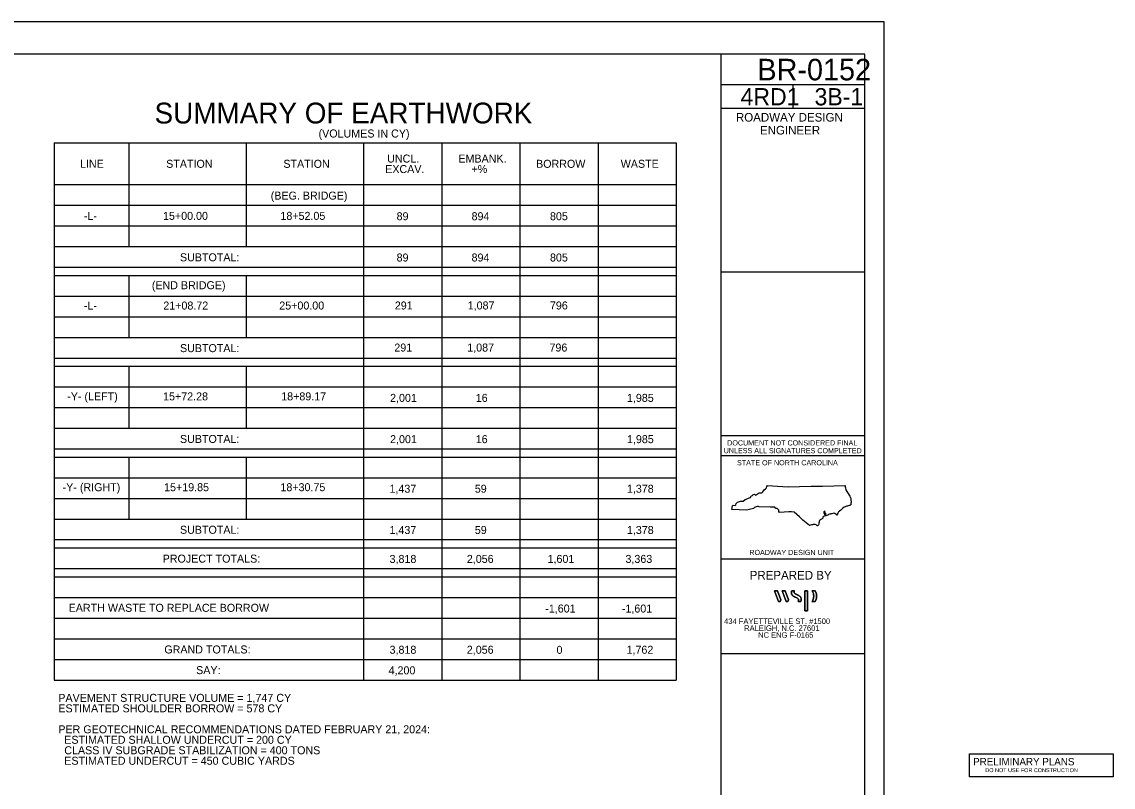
# Model space of a CAD drawing. Extents: x 1551694 to 1553358, y 810412 to 811095.
# Drawn here: x 1553203.1 to 1553355.1, y 810595.3 to 810701.9 of the extents above; entities that cross this region are included whole.
import ezdxf

# ---------------------------------------------------------------- set-up
doc = ezdxf.new("R2010")
doc.units = 0
for name, color, linetype in [('Construction Elements LEVEL', 7, 'Continuous'), ('Default', 7, 'Continuous'), ('Draft_Plan_Labels', 7, 'Continuous'), ('E_NCDOT_Vertical_Profile_Ground_Line', 7, 'Continuous'), ('P_HYD_Ditch_Flow_Arrow', 7, 'Continuous'), ('P_HYD_Pipe_RCP_15in_Class_III', 7, 'Continuous'), ('P_NCDOT_SS_Transition_Line', 7, 'Continuous'), ('Typical Terminator CELL', 7, 'Continuous'), ('V Ditch Special Lateral with PSRM Detail CELL', 7, 'Continuous')]:
    doc.layers.add(name, color=color, linetype=linetype)

msp = doc.modelspace()

# ---------------------------------------------------------------- linework, layer by layer
at = {"layer": 'Construction Elements LEVEL'}
for p, q in [((1553207.6, 810685.06), (1553294.23, 810685.06)), ((1553207.6, 810685.06), (1553207.6, 810610.26)), ((1553218.02, 810685.06), (1553218.02, 810670.63)), ((1553234.35, 810685.06), (1553234.35, 810670.63)), ((1553250.68, 810685.06), (1553250.68, 810610.26)), ((1553261.57, 810685.06), (1553261.57, 810610.26)), ((1553272.46, 810685.06), (1553272.46, 810610.26)), ((1553283.35, 810685.06), (1553283.35, 810610.26)), ((1553294.23, 810685.06), (1553294.23, 810610.26)), ((1553207.6, 810679.26), (1553294.23, 810679.26)), ((1553207.6, 810676.38), (1553294.23, 810676.38)), ((1553207.6, 810673.51), (1553294.23, 810673.51)), ((1553207.6, 810670.63), (1553294.23, 810670.63)), ((1553207.6, 810667.76), (1553294.23, 810667.76)), ((1553207.6, 810666.61), (1553294.23, 810666.61)), ((1553218.02, 810666.61), (1553218.02, 810657.98)), ((1553234.35, 810666.61), (1553234.35, 810657.98)), ((1553207.6, 810663.73), (1553294.23, 810663.73)), ((1553207.6, 810660.86), (1553294.23, 810660.86)), ((1553207.6, 810657.98), (1553294.23, 810657.98)), ((1553207.6, 810655.11), (1553294.23, 810655.11)), ((1553207.6, 810653.96), (1553294.23, 810653.96)), ((1553218.02, 810653.96), (1553218.02, 810645.33)), ((1553234.35, 810653.96), (1553234.35, 810645.33)), ((1553207.6, 810651.08), (1553294.23, 810651.08)), ((1553207.6, 810648.21), (1553294.23, 810648.21)), ((1553207.6, 810645.33), (1553294.23, 810645.33)), ((1553207.6, 810642.46), (1553294.23, 810642.46)), ((1553207.6, 810641.31), (1553294.23, 810641.31)), ((1553218.02, 810641.31), (1553218.02, 810632.68)), ((1553234.35, 810641.31), (1553234.35, 810632.68)), ((1553207.6, 810638.43), (1553294.23, 810638.43)), ((1553207.6, 810635.56), (1553294.23, 810635.56)), ((1553207.6, 810632.68), (1553294.23, 810632.68)), ((1553207.6, 810629.81), (1553294.23, 810629.81)), ((1553207.6, 810628.66), (1553294.23, 810628.66)), ((1553207.6, 810625.78), (1553294.23, 810625.78)), ((1553207.6, 810624.63), (1553294.23, 810624.63)), ((1553207.6, 810621.76), (1553294.23, 810621.76)), ((1553207.6, 810618.88), (1553294.23, 810618.88)), ((1553207.6, 810616.01), (1553294.23, 810616.01)), ((1553207.6, 810613.13), (1553294.23, 810613.13)), ((1553207.6, 810610.26), (1553294.23, 810610.26))]:
    msp.add_line(p, q, dxfattribs=at)
at = {"layer": 'Default'}
for p, q in [((1553308.47, 810621.19), (1553307.91, 810622.7)), ((1553307.91, 810622.7), (1553308.32, 810622.7)), ((1553308.32, 810622.7), (1553308.78, 810621.45)), ((1553309.56, 810621.19), (1553309, 810622.7)), ((1553309, 810622.7), (1553309.41, 810622.7)), ((1553309.41, 810622.7), (1553309.87, 810621.45)), ((1553312.12, 810619.91), (1553312.12, 810622.7)), ((1553312.12, 810622.7), (1553312.51, 810622.7)), ((1553312.51, 810622.7), (1553312.51, 810619.91)), ((1553308.69, 810621.19), (1553308.47, 810621.19)), ((1553308.78, 810621.45), (1553308.69, 810621.19)), ((1553309.77, 810621.19), (1553309.56, 810621.19)), ((1553309.87, 810621.45), (1553309.77, 810621.19)), ((1553312.51, 810619.91), (1553312.12, 810619.91))]:
    msp.add_line(p, q, dxfattribs=at)
for points in [[(1553308.32, 810622.7), (1553307.91, 810622.7), (1553308.47, 810621.19), (1553308.69, 810621.19), (1553308.78, 810621.45), (1553308.32, 810622.7)], [(1553309.41, 810622.7), (1553309, 810622.7), (1553309.56, 810621.19), (1553309.77, 810621.19), (1553309.87, 810621.45), (1553309.41, 810622.7)], [(1553312.51, 810619.91), (1553312.51, 810622.7), (1553312.12, 810622.7), (1553312.12, 810619.91), (1553312.51, 810619.91)]]:
    msp.add_lwpolyline(points, dxfattribs=at)
msp.add_lwpolyline([(1553335.08, 810596.79), (1553335.08, 810599.98), (1553355.08, 810599.98), (1553355.08, 810596.79)], close=True, dxfattribs=at)
for points in [[(1553310.28, 810622.48), (1553310.29, 810622.55), (1553310.3, 810622.63), (1553310.33, 810622.7), (1553310.33, 810622.7), (1553310.69, 810622.7), (1553310.69, 810622.7), (1553310.66, 810622.65), (1553310.63, 810622.55), (1553310.66, 810622.45), (1553310.69, 810622.37), (1553310.75, 810622.31), (1553310.83, 810622.26), (1553310.92, 810622.2), (1553311.02, 810622.17), (1553311.12, 810622.12), (1553311.22, 810622.07), (1553311.32, 810622.02), (1553311.41, 810621.95), (1553311.53, 810621.84), (1553311.61, 810621.71), (1553311.62, 810621.55), (1553311.62, 810621.53), (1553311.62, 810621.51), (1553311.62, 810621.49), (1553311.62, 810621.39), (1553311.6, 810621.29), (1553311.56, 810621.19), (1553311.56, 810621.19), (1553311.19, 810621.19), (1553311.19, 810621.19), (1553311.23, 810621.25), (1553311.26, 810621.34), (1553311.25, 810621.41), (1553311.24, 810621.6), (1553311.01, 810621.71), (1553310.81, 810621.79), (1553310.78, 810621.81), (1553310.76, 810621.82), (1553310.73, 810621.83), (1553310.64, 810621.87), (1553310.56, 810621.92), (1553310.49, 810621.98), (1553310.41, 810622.04), (1553310.35, 810622.1), (1553310.32, 810622.2), (1553310.29, 810622.28), (1553310.28, 810622.36), (1553310.28, 810622.45), (1553310.28, 810622.46), (1553310.28, 810622.47), (1553310.28, 810622.48)], [(1553310.28, 810622.48), (1553310.28, 810622.47), (1553310.28, 810622.46), (1553310.28, 810622.45), (1553310.28, 810622.36), (1553310.29, 810622.28), (1553310.32, 810622.2), (1553310.35, 810622.1), (1553310.41, 810622.04), (1553310.49, 810621.98), (1553310.56, 810621.92), (1553310.64, 810621.87), (1553310.73, 810621.83), (1553310.76, 810621.82), (1553310.78, 810621.81), (1553310.81, 810621.79), (1553311.01, 810621.71), (1553311.24, 810621.6), (1553311.25, 810621.41), (1553311.26, 810621.34), (1553311.23, 810621.25), (1553311.19, 810621.19), (1553311.19, 810621.19), (1553311.56, 810621.19), (1553311.56, 810621.19), (1553311.6, 810621.29), (1553311.62, 810621.39), (1553311.62, 810621.49), (1553311.62, 810621.51), (1553311.62, 810621.53), (1553311.62, 810621.55), (1553311.61, 810621.71), (1553311.53, 810621.84), (1553311.41, 810621.95), (1553311.32, 810622.02), (1553311.22, 810622.07), (1553311.12, 810622.12), (1553311.02, 810622.17), (1553310.92, 810622.2), (1553310.83, 810622.26), (1553310.75, 810622.31), (1553310.69, 810622.37), (1553310.66, 810622.45), (1553310.63, 810622.55), (1553310.66, 810622.65), (1553310.69, 810622.7), (1553310.69, 810622.7), (1553310.33, 810622.7), (1553310.33, 810622.7), (1553310.3, 810622.63), (1553310.29, 810622.55), (1553310.28, 810622.48)], [(1553313.37, 810621.95), (1553313.37, 810622.26), (1553313.26, 810622.53), (1553313.11, 810622.7), (1553313.11, 810622.7), (1553313.55, 810622.7), (1553313.55, 810622.7), (1553313.69, 810622.53), (1553313.78, 810622.23), (1553313.78, 810621.95), (1553313.78, 810621.95), (1553313.78, 810621.95), (1553313.78, 810621.95), (1553313.78, 810621.67), (1553313.69, 810621.37), (1553313.55, 810621.19), (1553313.55, 810621.19), (1553313.11, 810621.19), (1553313.11, 810621.19), (1553313.26, 810621.37), (1553313.37, 810621.63), (1553313.37, 810621.95), (1553313.37, 810621.95), (1553313.37, 810621.95), (1553313.37, 810621.95)], [(1553313.37, 810621.95), (1553313.37, 810621.95), (1553313.37, 810621.95), (1553313.37, 810621.95), (1553313.37, 810621.63), (1553313.26, 810621.37), (1553313.11, 810621.19), (1553313.11, 810621.19), (1553313.55, 810621.19), (1553313.55, 810621.19), (1553313.69, 810621.37), (1553313.78, 810621.67), (1553313.78, 810621.95), (1553313.78, 810621.95), (1553313.78, 810621.95), (1553313.78, 810621.95), (1553313.78, 810622.23), (1553313.69, 810622.53), (1553313.55, 810622.7), (1553313.55, 810622.7), (1553313.11, 810622.7), (1553313.11, 810622.7), (1553313.26, 810622.53), (1553313.37, 810622.26), (1553313.37, 810621.95)]]:
    msp.add_open_spline(points, degree=3, dxfattribs=at)
at = {"layer": 'Draft_Plan_Labels'}
msp.add_line((1553317.75, 810637.34), (1553317.75, 810637.35), dxfattribs=at)
for points in [[(1553301.95, 810634.02), (1553302.08, 810634.51), (1553302.16, 810634.6), (1553302.42, 810634.58), (1553302.51, 810634.67), (1553302.58, 810634.86), (1553302.78, 810635.02), (1553303.16, 810635.19), (1553303.55, 810635.19), (1553303.83, 810635.39), (1553304.2, 810635.55), (1553304.38, 810635.65), (1553304.56, 810635.66), (1553304.68, 810635.93), (1553304.86, 810635.98), (1553304.92, 810636.07), (1553305.11, 810636.16), (1553305.28, 810636.03), (1553305.37, 810636.04), (1553305.48, 810636.14), (1553305.76, 810636.34), (1553306.14, 810636.35), (1553306.31, 810636.49), (1553306.46, 810636.77), (1553306.64, 810636.9), (1553306.82, 810637.03), (1553306.85, 810637.21), (1553306.96, 810637.35)], [(1553306.96, 810637.35), (1553308.33, 810637.25), (1553309.84, 810637.19), (1553311.41, 810637.21), (1553313.01, 810637.24), (1553314.58, 810637.26), (1553316.2, 810637.31), (1553317.71, 810637.35), (1553317.75, 810637.35)], [(1553312.79, 810631.76), (1553311.87, 810632.52), (1553311.39, 810633.01), (1553310.67, 810633.63), (1553310.29, 810633.69), (1553309.9, 810633.67), (1553308.6, 810633.61), (1553308.53, 810633.71), (1553308.53, 810633.8), (1553308.52, 810633.9), (1553308.28, 810634.16), (1553308.1, 810634.14), (1553307.97, 810634.32), (1553307.3, 810634.33), (1553305.8, 810634.4), (1553305.7, 810634.42), (1553305.52, 810634.42), (1553305.15, 810634.29), (1553304.97, 810634.14), (1553304.42, 810634.03), (1553304.03, 810633.94), (1553302.98, 810633.95), (1553301.95, 810634.02)]]:
    msp.add_lwpolyline(points, dxfattribs=at)
for points in [[(1553317.75, 810637.34), (1553317.78, 810637.04), (1553318.33, 810635.99), (1553318.53, 810635.52), (1553318.57, 810635.04), (1553318.55, 810634.73)], [(1553318.55, 810634.73), (1553318.5, 810634.64), (1553318.41, 810634.59), (1553317.95, 810634.46)], [(1553317.95, 810634.46), (1553317.6, 810634.32), (1553316.98, 810633.78), (1553316.73, 810633.51), (1553316.61, 810633.24), (1553316.34, 810633.44), (1553315.77, 810633.39), (1553315.56, 810633.36), (1553315.11, 810633.15), (1553315.02, 810633.21), (1553315.01, 810633.3), (1553315.09, 810633.39), (1553314.96, 810633.55), (1553314.99, 810633.64), (1553314.84, 810633.76), (1553314.79, 810633.67), (1553314.79, 810633.49), (1553314.87, 810633.4), (1553314.87, 810633.31), (1553314.99, 810633.13), (1553314.68, 810633.02), (1553314.65, 810632.82), (1553314.37, 810632.64), (1553314.12, 810632.24), (1553313.97, 810631.78), (1553313.89, 810631.74), (1553313.71, 810631.88), (1553313.41, 810631.91), (1553313.32, 810631.91), (1553312.79, 810631.76)]]:
    msp.add_spline(points, degree=3, dxfattribs=at)
at = {"layer": 'E_NCDOT_Vertical_Profile_Ground_Line'}
for p, q in [((1553239.93, 810685.05), (1553239.93, 810685.05)), ((1553241.38, 810685.03), (1553241.38, 810685.03)), ((1553243.48, 810685.07), (1553243.48, 810685.07)), ((1553244.78, 810685.05), (1553244.78, 810685.05))]:
    msp.add_line(p, q, dxfattribs=at)
at = {"layer": 'P_HYD_Pipe_RCP_15in_Class_III'}
for p, q in [((1553320.5, 810697.43), (1552990.5, 810697.43)), ((1553300.5, 810486.43), (1553300.51, 810697.43)), ((1553320.5, 810486.43), (1553320.5, 810697.43)), ((1553320.5, 810693.15), (1553300.51, 810693.15)), ((1553310.5, 810689.85), (1553310.5, 810693.15)), ((1553320.5, 810689.85), (1553300.51, 810689.85)), ((1553320.5, 810667.05), (1553300.51, 810667.05)), ((1553320.5, 810644.25), (1553300.51, 810644.25)), ((1553320.5, 810641.49), (1553300.51, 810641.49)), ((1553320.5, 810627.09), (1553300.51, 810627.09)), ((1553320.5, 810613.89), (1553300.51, 810613.89))]:
    msp.add_line(p, q, dxfattribs=at)
msp.add_circle((1553300.51, 810689.85), 0.012, dxfattribs=at)
at = {"layer": 'V Ditch Special Lateral with PSRM Detail CELL'}
for p, q in [((1553323.21, 810701.93), (1552983.21, 810701.93)), ((1553323.21, 810481.93), (1553323.21, 810701.93))]:
    msp.add_line(p, q, dxfattribs=at)

# ---------------------------------------------------------------- texts
at = {"layer": 'Default'}
for s, height, p in [('(BEG. BRIDGE)', 1.1145, (1553237.76, 810677.17)), ('-L-', 1.114, (1553211.74, 810674.35)), ('SUBTOTAL:', 1.114, (1553225.12, 810668.58)), ('(END BRIDGE)', 1.1145, (1553221.2, 810664.69)), ('-L-', 1.114, (1553211.74, 810661.86)), ('SUBTOTAL:', 1.114, (1553225.12, 810655.93)), ('-Y- (LEFT)', 1.114, (1553209.42, 810649.21)), ('SUBTOTAL:', 1.114, (1553225.12, 810643.28)), ('-Y- (RIGHT)', 1.1145, (1553208.78, 810636.56)), ('SUBTOTAL:', 1.114, (1553225.12, 810630.63)), ('PROJECT TOTALS:', 1.1145, (1553222.71, 810626.61)), ('EARTH WASTE TO REPLACE BORROW', 1.1145, (1553209.62, 810619.76)), ('GRAND TOTALS:', 1.1145, (1553222.94, 810613.96)), ('SAY:', 1.114, (1553227.37, 810611.08))]:
    msp.add_text(s, height=height, rotation=360, dxfattribs=at).set_placement(p)
for s, height, p in [('15+00.00', 1.114, (1553222.76, 810674.35)), ('18+52.05', 1.114, (1553239.11, 810674.35)), ('21+08.72', 1.114, (1553222.8, 810661.86)), ('25+00.00', 1.114, (1553238.95, 810661.86)), ('15+72.28', 1.114, (1553222.77, 810649.21)), ('18+89.17', 1.114, (1553239.22, 810649.21)), ('15+19.85', 1.114, (1553222.91, 810636.56)), ('18+30.75', 1.114, (1553239.11, 810636.56)), ('PAVEMENT STRUCTURE VOLUME = 1,747 CY', 1.1145, (1553208.18, 810607.22)), ('ESTIMATED SHOULDER BORROW = 578 CY', 1.1145, (1553208.18, 810605.76)), ('PER GEOTECHNICAL RECOMMENDATIONS DATED FEBRUARY 21, 2024:', 1.1145, (1553208.18, 810602.84)), ('  ESTIMATED SHALLOW UNDERCUT = 200 CY', 1.1145, (1553208.18, 810601.38)), ('  CLASS IV SUBGRADE STABILIZATION = 400 TONS', 1.1145, (1553208.18, 810599.92)), ('  ESTIMATED UNDERCUT = 450 CUBIC YARDS', 1.1145, (1553208.18, 810598.46))]:
    msp.add_text(s, height=height, dxfattribs=at).set_placement(p)
at = {"layer": 'E_NCDOT_Vertical_Profile_Ground_Line'}
for s, height, rotation, p in [('SUMMARY OF EARTHWORK', 2.9023, 0.0119, (1553221.58, 810687.77)), ('(VOLUMES IN CY)', 1.1145, 360, (1553244.42, 810685.82)), ('UNCL.', 1.114, 360, (1553253.97, 810682.33)), ('EMBANK.', 1.114, 360, (1553263.89, 810682.33)), ('LINE', 1.114, 360, (1553211.2, 810681.6)), ('STATION', 1.114, 360, (1553223.2, 810681.6)), ('STATION', 1.114, 360, (1553239.52, 810681.6)), ('EXCAV.', 1.114, 360, (1553253.7, 810680.87)), ('+%', 1.114, 360, (1553265.72, 810680.87)), ('BORROW', 1.114, 360, (1553274.71, 810681.6)), ('WASTE', 1.114, 360, (1553286.5, 810681.6)), ('89', 1.114, 360, (1553255.29, 810674.3)), ('894', 1.114, 360, (1553265.73, 810674.3)), ('805', 1.114, 360, (1553276.65, 810674.3)), ('89', 1.114, 360, (1553255.29, 810668.55)), ('894', 1.114, 360, (1553265.73, 810668.55)), ('805', 1.114, 360, (1553276.65, 810668.55)), ('291', 1.114, 360, (1553255.04, 810661.87)), ('1,087', 1.114, 360, (1553265.19, 810661.87)), ('796', 1.114, 360, (1553276.64, 810661.87)), ('291', 1.114, 360, (1553254.97, 810656.01)), ('1,087', 1.114, 360, (1553265.13, 810656.01)), ('796', 1.114, 360, (1553276.58, 810656.01)), ('2,001', 1.114, 360, (1553254.38, 810649)), ('16', 1.114, 360, (1553266.31, 810649)), ('1,985', 1.114, 360, (1553287.37, 810649)), ('2,001', 1.114, 360, (1553254.38, 810643.25)), ('16', 1.114, 360, (1553266.31, 810643.25)), ('1,985', 1.114, 360, (1553287.37, 810643.25)), ('1,437', 1.114, 360, (1553254.3, 810636.35)), ('59', 1.114, 360, (1553266.18, 810636.35)), ('1,378', 1.114, 360, (1553287.36, 810636.35)), ('1,437', 1.114, 360, (1553254.3, 810630.6)), ('59', 1.114, 360, (1553266.18, 810630.6)), ('1,378', 1.114, 360, (1553287.36, 810630.6)), ('3,818', 1.114, 360, (1553254.31, 810626.57)), ('2,056', 1.114, 360, (1553265.07, 810626.57)), ('1,601', 1.114, 360, (1553276.31, 810626.57)), ('3,363', 1.114, 360, (1553287.16, 810626.57)), ('-1,601', 1.114, 360, (1553275.99, 810619.66)), ('-1,601', 1.114, 360, (1553286.66, 810619.66)), ('3,818', 1.114, 360, (1553254.31, 810613.92)), ('2,056', 1.114, 360, (1553265.07, 810613.92)), ('0', 1.11, 360, (1553277.56, 810613.91)), ('1,762', 1.114, 360, (1553287.31, 810613.92)), ('4,200', 1.114, 360, (1553254.17, 810611.05))]:
    msp.add_text(s, height=height, rotation=rotation, dxfattribs=at).set_placement(p)
at = {"layer": 'P_HYD_Ditch_Flow_Arrow'}
for s, height, p in [('PRELIMINARY PLANS', 1.0204, (1553335.58, 810598.38)), ('DO NOT USE FOR CONSTRUCTION', 0.551, (1553337.27, 810597.43))]:
    msp.add_text(s, height=height, rotation=360, dxfattribs=at).set_placement(p)
at = {"layer": 'P_NCDOT_SS_Transition_Line'}
for s, p in [('434 FAYETTEVILLE ST. #1500', (1553300.9, 810618.07)), ('RALEIGH, N.C. 27601', (1553303.69, 810617.11)), ('NC ENG F-0165', (1553305.64, 810616.15))]:
    msp.add_text(s, height=0.7601, rotation=360, dxfattribs=at).set_placement(p)
at = {"layer": 'Typical Terminator CELL'}
for s, height, p in [('BR-0152', 3, (1553305.53, 810693.78)), ('4RD1', 2.4, (1553303.19, 810690.3)), ('3B-1', 2.4, (1553313.49, 810690.3)), ('ROADWAY DESIGN', 1.2, (1553302.54, 810688.04)), ('ENGINEER', 1.2, (1553305.89, 810686.24)), ('UNLESS ALL SIGNATURES COMPLETED', 0.72, (1553300.84, 810641.85)), ('DOCUMENT NOT CONSIDERED FINAL', 0.72, (1553301.33, 810642.93)), ('STATE OF NORTH CAROLINA', 0.72, (1553302.7, 810640.17)), ('ROADWAY DESIGN UNIT', 0.72, (1553304.41, 810627.67)), ('PREPARED BY', 1.2, (1553304.46, 810624.26))]:
    msp.add_text(s, height=height, dxfattribs=at).set_placement(p)

doc.saveas('drawing.dxf')
